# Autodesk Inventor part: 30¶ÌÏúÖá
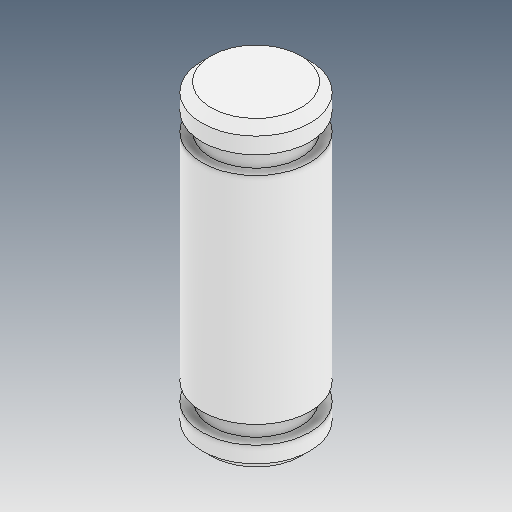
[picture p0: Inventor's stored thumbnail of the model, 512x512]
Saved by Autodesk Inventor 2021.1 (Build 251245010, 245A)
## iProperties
Created: 2021-05
Part Number: 30¶ÌÏúÖá
Material: Ogólny
Document SubType Name: Modeling
Designer: user
Density: 1 g/cm^3
Appearance: Domyślna
Author: user
Revision Number: ÈÎºÎ
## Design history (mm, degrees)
feature "ÊäÈë1"
node "Bryła1"
